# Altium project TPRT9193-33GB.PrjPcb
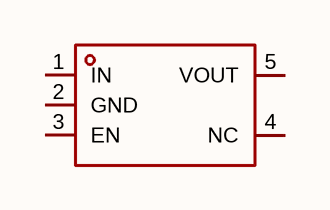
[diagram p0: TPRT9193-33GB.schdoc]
1 sheet, 1 parts. Net scope: global (net labels, ports and power ports of the same name join across sheets).

## Sheet TPRT9193-33GB.schdoc
size 127 x 101 mm

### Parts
U?  tprt9193-33gb  [SOT-23-5_L3.0-W1.7-P0.95-LS2.8-BL]  (value not drawn)

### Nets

Not connected (* = marked no-connect by the designer): U? 1(IN) 2(GND) 3(EN) 4(NC) 5(VOUT)

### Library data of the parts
U? = tprt9193-33gb: 输出极性:正极;工作电压:6V;输出电压:3.3V;输出电流:300mA;电源纹波抑制比(PSRR):70dB@(1kHz);输出类型:固定;; Manufacturer: TECH PUBLIC(台舟); AddInBom: yes; ModelId: 0a2a1b8f50944f73965918ad6e5fe167; ModelName: SOT-23-5_L2.9-W1.6-H1.1-LS2.8-P0.95; ModelTransform: 118.60433,114.173,0,90,0,0,0.0005,0.0005,0; Output Configuration: 正极; Voltage - Supply: 6V; Output Voltage: 3.3V; Output Current: 300mA; Voltage Dropout: 90mV@(100mA)；230mV@(200mA); standby current: 70uA; Noise: 50uVrms; Output Type: 固定; Number of Outputs: 1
